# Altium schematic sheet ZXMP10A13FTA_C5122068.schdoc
size 127 x 101 mm
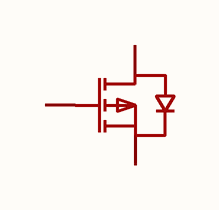
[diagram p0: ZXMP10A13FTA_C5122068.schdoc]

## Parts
Q?  zxmp10a13fta_c5122068  [SOT-23-3_L2.9-W1.3-P1.90-LS2.4-BR]  (value not drawn)

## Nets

Not connected (* = marked no-connect by the designer): Q? 1(G) 2(S) 3(D)

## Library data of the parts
Q? = zxmp10a13fta_c5122068: 数量:1个P沟道;漏源电压(Vdss):100V;连续漏极电流(Id):1A;导通电阻(RDS(on)):500mΩ@10V;耗散功率(Pd):1.25W;阈值电压(Vgs(th)):2V;; Manufacturer: TECH PUBLIC(台舟); AddInBom: yes; ModelId: c62791f0466c4ae2a892c056b845b0ca; ModelName: SOT-23-3P_L2.9-W1.3-H1.0-LS2.4-P0.95; ModelTransform: 98.425,114.173,0,180,0,0,0.0005,-0.0005,0; Number: 1个P沟道; Drain to Source Voltage: 100V; Current - Continuous Drain(Id): 1A; Pd - Power Dissipation: 1.25W; Gate Threshold Voltage (Vgs(th)): 2V; Gate Charge(Qg): 8nC@10V; Input Capacitance(Ciss): 448pF; Reverse Transfer Capacitance (Crss@Vds): 21pF; Type: P沟道; Output Capacitance(Coss): 28pF; Vgs: ±20V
